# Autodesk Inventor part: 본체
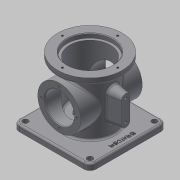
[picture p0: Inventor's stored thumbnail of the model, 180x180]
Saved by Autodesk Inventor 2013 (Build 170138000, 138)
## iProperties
Created: 2017-08
Part Number: 본체
Material: 일반
Document SubType Name: Modeling
Designer: mduedu
Density: 1 g/cm^3
Mass: 350.938 g
Surface Area: 966.502 cm^2
Volume: 350.938 cm^3
Author: mduedu
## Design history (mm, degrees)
sketch "스케치1"
  geometry: L1 (-62.5, -62.5)-(62.5, -62.5); L2 (62.5, -62.5)-(62.5, 62.5); L3 (62.5, 62.5)-(-62.5, 62.5); L4 (-62.5, 62.5)-(-62.5, -62.5); L5 (-62.5, -62.5)-(62.5, 62.5); L6 (62.5, -62.5)-(-62.5, 62.5); 1 further point
  constraints: 12 end point, 2 midpoint, 2 parallel, 1 horizontal, 1 perpendicular
  dimensions: "d232" = 125 distance of L3.end L2.end; "d233" = 125 distance of L2.end L1.end
extrude "돌출1" new body sketch "스케치1" distance "d5" = 10; taper "d6" = 0 deg
sketch "스케치2"
  geometry: C1 r 38 at (0, 0); 1 further point
  constraints: 1 centre point, 1 coincident
  dimensions: "d111" = 76 diameter of C1
extrude "돌출2" join sketch "스케치2" distance "d12" = 88; taper "d13" = 0 deg
sketch "스케치3"
  geometry: C1 r 52.5 at (0, 0); 1 further point
  constraints: 1 centre point, 1 coincident
  dimensions: "d114" = 105 diameter of C1
extrude "돌출3" join sketch "스케치3" distance "d19" = 10; taper "d20" = 0 deg
sketch "스케치4"
  geometry: C1 r 33 at (0, 0); 1 further point
  constraints: 1 centre point, 1 coincident
  dimensions: "d115" = 66 diameter of C1
extrude "돌출4" cut sketch "스케치4" distance "d26" = 86; taper "d27" = 0 deg
sketch "스케치5"
  geometry: C1 r 37 at (0, 0); 1 further point
  constraints: 1 centre point, 1 coincident
  dimensions: "d116" = 74 diameter of C1
extrude "돌출5" cut sketch "스케치5" distance "d29" = 7; taper "d30" = 0 deg
node "작업 평면1"
sketch "스케치18"
  geometry: L1 (-62.5, 0)-(62.5, 0) reference; C1 r 35 at (0, 54); 1 further point
  constraints: 1 centre point, 1 vertical alignment
  dimensions: "d118" = 70 diameter of C1; "d234" = 54 distance from line of C1.centre L1
extrude "돌출9" join sketch "스케치18" stored distance "d120" = 10; taper "d121" = 0 deg
hole "구멍8" diameter "d124" = 48; stored, may be unused: countersink angle "d128" = 90 deg, drill point angle "d130" = 118 deg; dims "d122" = 10, "d123" = 10, "d125" = 6, "d126" = 4, "d127" = 2, "d129" = 8
sketch "스케치9"
  geometry: C1 r 33 at (0, 0); 1 further point
  constraints: 1 centre point, 1 coincident
  dimensions: "d131" = 66 diameter of C1
extrude "돌출8" cut sketch "스케치9" distance "d43" = 16; taper "d44" = 0 deg
node "작업 평면2"
fillet "모깎기9" dims "d137" = 3
fillet "모깎기10" dims "d138" = 3
chamfer "모따기2" distance "d139" = 1; stored, may be unused: second distance "d140" = 2, angle "d141" = 45 deg
fillet "모깎기11" dims "d142" = 3
fillet "모깎기12" dims "d143" = 3
fillet "모깎기13" dims "d144" = 3
node "작업 평면3"
sketch "스케치20"
  geometry: L1 (108, -52.5)-(108, 52.5) reference; L2 (37, 7)-(71, 7); L3 (37, -7)-(71, -7); L4 (0, -33)-(0, 33) reference; A1 r 7 centre (37, 0) between (37, 7) and (37, -7); A2 r 7 centre (71, 0) between (71, 7) and (71, -7); 1 further point
  constraints: 4 end point, 4 point on circle, 3 tangent, 2 centre point, 2 horizontal alignment, 1 parallel, 1 perpendicular
  dimensions: "d203" = 14 diameter of A1; "d206" = 30 distance edge to line of A2 L1; "d207" = 48 dimension on A2 A1 (derived); "d236" = 30 distance edge to line of A1 L4
extrude "돌출10" join sketch "스케치20" stored distance "d152" = 10; taper "d153" = 10 deg
sketch "스케치21"
  geometry: C1 r 7 at (0, 71) reference; C2 r 7 at (0, 37) reference; 3 further points
  constraints: 2 coincident
hole "구멍12" sketch "스케치21" at (0, 71), (0, 37) diameter "d219" = 4.134; stored, may be unused: countersink angle "d223" = 90 deg, drill point angle "d225" = 118 deg; dims "d220" = 6, "d221" = 4, "d222" = 2, "d224" = 8
fillet "모깎기18" dims "d229" = 3
sketch "스케치23"
  geometry: C1 r 20 at (0, 0); 1 further point
  constraints: 1 centre point, 1 coincident
  dimensions: "d168" = 40 diameter of C1
extrude "돌출12" cut sketch "스케치23" stored distance "d169" = 148.25; taper "d170" = 0 deg
sketch "스케치28"
  geometry: L1 (62.5, -62.5)-(62.5, 62.5) reference; 2 further points
  constraints: 1 horizontal alignment, 1 other
  dimensions: "d238" = 10 distance from line of point (52.5, 0) L1
feature "엠보싱4" sketch "스케치28" dims "d239" = 0.5, "d240" = 0
sketch "스케치25" dims "d178" = 58
  geometry: C1 r 35 at (0, 0) reference; 3 further points
  constraints: 2 vertical alignment, 1 coincident, 2 other
hole "구멍10" sketch "스케치25" at (0, 29) diameter "d179" = 3.242; stored, may be unused: countersink angle "d183" = 90 deg, drill point angle "d185" = 118 deg; dims "d180" = 4, "d181" = 4, "d182" = 2, "d184" = 6
sketch "스케치26" dims "d189" = 90
  geometry: 3 further points
  constraints: 2 vertical alignment, 1 coincident, 2 other
hole "구멍11" sketch "스케치26" at (0, 45) diameter "d190" = 3.242; stored, may be unused: countersink angle "d194" = 90 deg, drill point angle "d196" = 118 deg; dims "d191" = 4, "d192" = 4, "d193" = 2, "d195" = 6
chamfer "모따기4" distance "d200" = 1; stored, may be unused: second distance "d201" = 2, angle "d202" = 45 deg
fillet "모깎기19" dims "d241" = 10
sketch "스케치29"
  geometry: A1 r 10 centre (-52.5, 52.5) between (-52.5, 62.5) and (-62.5, 52.5) reference; A2 r 10 centre (52.5, 52.5) between (62.5, 52.5) and (52.5, 62.5) reference; A3 r 10 centre (52.5, -52.5) between (52.5, -62.5) and (62.5, -52.5) reference; A4 r 10 centre (-52.5, -52.5) between (-62.5, -52.5) and (-52.5, -62.5) reference; 5 further points
  constraints: 4 coincident
hole "구멍13" sketch "스케치29" at (-52.5, 52.5), (52.5, 52.5), (52.5, -52.5), (-52.5, -52.5) diameter "d242" = 9; stored, may be unused: countersink angle "d246" = 90 deg, drill point angle "d248" = 118 deg; dims "d243" = 6, "d244" = 4, "d245" = 2, "d247" = 8
fillet "모깎기20" dims "d249" = 3
node "솔리드1"
mirror "대칭2"
pattern_circular "원형 패턴1" dims angle "d187" = 360 deg
mirror "대칭3"
pattern_circular "원형 패턴2" dims angle "d198" = 360 deg
other parameters: "d147" = 58
